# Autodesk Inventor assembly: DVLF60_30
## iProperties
Created: 2010-03
Part Number: DVLF60_30
Document SubType Name: Assembly
Designer: TB
Mass: 1043.98 g
Surface Area: 1801.01 cm^2
Volume: 1043.98 cm^3
Density: 1 g/cm^3
Description: KM DVLF 60/30 - 100 mm
Slaglengde: 100.000 mm
Author: TB
